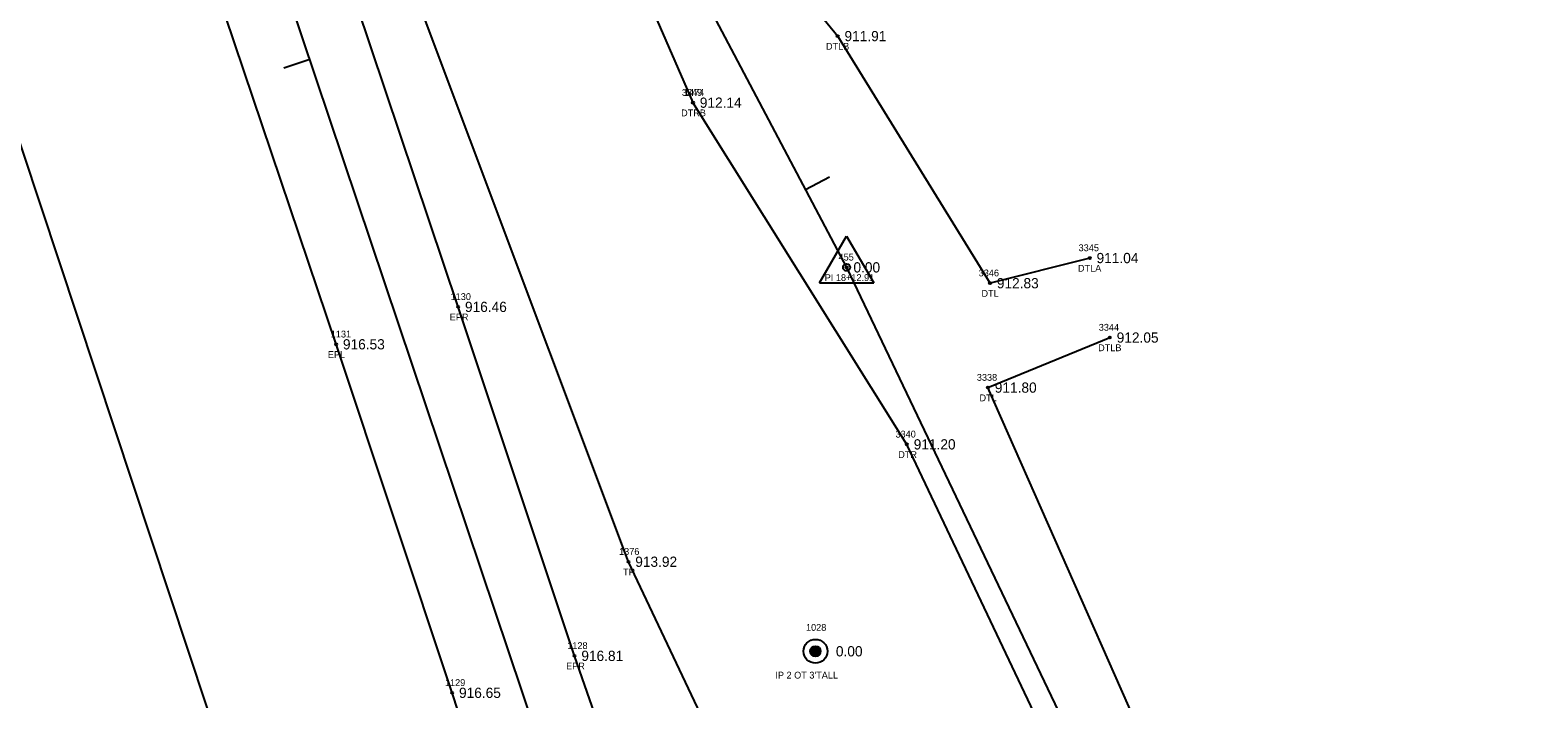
# Model space of a CAD drawing. Extents: x 1528109 to 1531398, y 1157799 to 1162548.
# Drawn here: x 1529538.8 to 1529759.7, y 1160387.6 to 1160485.7 of the extents above; entities that cross this region are included whole.
import ezdxf

# ---------------------------------------------------------------- set-up
doc = ezdxf.new("R2010")
doc.units = 0
for name, color, linetype in [('RD_EX_DV_Prop_txCode', 7, 'Continuous'), ('RD_EX_DV_PropPin', 7, 'Continuous'), ('RD_EX_H2O', 7, 'Continuous'), ('RD_EX_H2O_txCode', 7, 'Continuous'), ('RD_EX_Road', 7, 'Continuous'), ('RD_EX_Road_txCode', 7, 'Continuous'), ('RD_EX_TX_DV_Prop_ELEV', 7, 'Continuous'), ('RD_EX_TX_H2O_ELEV', 7, 'Continuous'), ('RD_EX_TX_Road_ELEV', 7, 'Continuous'), ('RD_EX_TX_VEG_ELEV', 7, 'Continuous'), ('RD_EX_VEG', 7, 'Continuous'), ('RD_EX_VEG_txCode', 7, 'Continuous'), ('RD_HC_Cl', 7, 'Continuous'), ('RD_HC_Data', 7, 'Continuous'), ('RD_HC_Data_Tic', 7, 'Continuous'), ('RD_HC_Survey_ELEV', 7, 'Continuous'), ('RD_HC_txCode', 7, 'Continuous'), ('RD_SMD_Locator', 7, 'Continuous')]:
    doc.layers.add(name, color=color, linetype=linetype)

msp = doc.modelspace()

# ---------------------------------------------------------------- linework, layer by layer
at = {"layer": 'RD_EX_DV_PropPin'}
for p, q in [((1529653.09, 1160394.39), (1529653.09, 1160394.78)), ((1529653.12, 1160394.29), (1529653.12, 1160394.89)), ((1529653.16, 1160394.22), (1529653.16, 1160394.96)), ((1529653.19, 1160394.16), (1529653.19, 1160395.01)), ((1529653.23, 1160394.11), (1529653.23, 1160395.06)), ((1529653.26, 1160394.07), (1529653.26, 1160395.1)), ((1529653.3, 1160394.04), (1529653.3, 1160395.14)), ((1529653.33, 1160394.01), (1529653.33, 1160395.17)), ((1529653.37, 1160393.98), (1529653.37, 1160395.2)), ((1529653.4, 1160393.95), (1529653.4, 1160395.22)), ((1529653.44, 1160393.93), (1529653.44, 1160395.24)), ((1529653.47, 1160393.91), (1529653.47, 1160395.26)), ((1529653.51, 1160393.89), (1529653.51, 1160395.28)), ((1529653.54, 1160393.88), (1529653.54, 1160395.3)), ((1529653.58, 1160393.87), (1529653.58, 1160395.31)), ((1529653.61, 1160393.86), (1529653.61, 1160395.32)), ((1529653.65, 1160393.85), (1529653.65, 1160395.33)), ((1529653.68, 1160393.84), (1529653.68, 1160395.34)), ((1529653.72, 1160393.83), (1529653.72, 1160395.34)), ((1529653.75, 1160393.83), (1529653.75, 1160395.35)), ((1529653.79, 1160393.83), (1529653.79, 1160395.35)), ((1529653.82, 1160393.83), (1529653.82, 1160395.35)), ((1529653.86, 1160393.83), (1529653.86, 1160395.35)), ((1529653.89, 1160393.83), (1529653.89, 1160395.35)), ((1529653.93, 1160393.83), (1529653.93, 1160395.34)), ((1529653.96, 1160393.84), (1529653.96, 1160395.34)), ((1529654, 1160393.85), (1529654, 1160395.33)), ((1529654.03, 1160393.86), (1529654.03, 1160395.32)), ((1529654.07, 1160393.87), (1529654.07, 1160395.31)), ((1529654.1, 1160393.88), (1529654.1, 1160395.3)), ((1529654.14, 1160393.89), (1529654.14, 1160395.28)), ((1529654.17, 1160393.91), (1529654.17, 1160395.26)), ((1529654.21, 1160393.93), (1529654.21, 1160395.24)), ((1529654.24, 1160393.95), (1529654.24, 1160395.22)), ((1529654.28, 1160393.98), (1529654.28, 1160395.2)), ((1529654.31, 1160394.01), (1529654.31, 1160395.17)), ((1529654.35, 1160394.04), (1529654.35, 1160395.14)), ((1529654.38, 1160394.07), (1529654.38, 1160395.1)), ((1529654.42, 1160394.11), (1529654.42, 1160395.06)), ((1529654.45, 1160394.16), (1529654.45, 1160395.01)), ((1529654.49, 1160394.22), (1529654.49, 1160394.96)), ((1529654.52, 1160394.29), (1529654.52, 1160394.89)), ((1529654.56, 1160394.39), (1529654.56, 1160394.78))]:
    msp.add_line(p, q, dxfattribs=at)
for radius in [1.75, 0.761]:
    msp.add_circle((1529653.82, 1160394.59), radius, dxfattribs=at)
at = {"layer": 'RD_EX_H2O'}
for points in [[(1529598.94, 1160572.79), (1529622.38, 1160527.22), (1529657.08, 1160484.79)], [(1529591.59, 1160568.48), (1529614.58, 1160524.05), (1529635.88, 1160475.03)], [(1529694.01, 1160452.25), (1529679.4, 1160448.56), (1529657.08, 1160484.79)], [(1529721.68, 1160311.69), (1529699.45, 1160356.92), (1529667.22, 1160424.93), (1529635.88, 1160475.03)], [(1529726.41, 1160311.29), (1529711.44, 1160359.97), (1529679.1, 1160433.25), (1529696.96, 1160440.59)]]:
    msp.add_lwpolyline(points, dxfattribs=at)
at = {"layer": 'RD_EX_Road'}
for points in [[(1529638.19, 1160337.41), (1529618.52, 1160393.92), (1529601.47, 1160445.09), (1529582.35, 1160502.18), (1529566.78, 1160548.91), (1529548.34, 1160605.67), (1529547.84, 1160613.14)], [(1529619.36, 1160331.12), (1529600.6, 1160388.5), (1529583.59, 1160439.6), (1529564.67, 1160495.86), (1529548.92, 1160543.15), (1529530.19, 1160599.08), (1529525.69, 1160605.63)]]:
    msp.add_lwpolyline(points, dxfattribs=at)
at = {"layer": 'RD_EX_VEG'}
for points in [[(1529712.92, 1160313.49), (1529665.06, 1160326.09), (1529626.42, 1160407.72), (1529580.03, 1160531.48), (1529510.74, 1160760.21), (1529455.97, 1160902.21), (1529420.7, 1161006.64), (1529376.36, 1161143.49), (1529336.53, 1161275.85), (1529306.04, 1161391.66)], [(1529543.38, 1160321.88), (1529583.48, 1160329.53), (1529467.47, 1160679.92), (1529425.09, 1160802.81), (1529349.9, 1161010.59), (1529312.85, 1161137.15)]]:
    msp.add_lwpolyline(points, dxfattribs=at)
at = {"layer": 'RD_HC_Cl'}
for p, q in [((1529913.5, 1159487.74), (1529527.85, 1160635.77)), ((1529598.3, 1160564.55), (1529658.39, 1160450.88)), ((1529658.39, 1160450.88), (1529753.92, 1160250.44))]:
    msp.add_line(p, q, dxfattribs=at)
at = {"layer": 'RD_HC_Data'}
for p, q in [((1529654.42, 1160448.59), (1529658.39, 1160455.47)), ((1529658.39, 1160455.47), (1529662.36, 1160448.59)), ((1529654.42, 1160448.59), (1529662.36, 1160448.59))]:
    msp.add_line(p, q, dxfattribs=at)
msp.add_circle((1529658.39, 1160450.88), 0.529, dxfattribs=at)
at = {"layer": 'RD_HC_Data_Tic'}
for p, q in [((1529579.72, 1160481.35), (1529575.93, 1160480.08)), ((1529652.36, 1160462.29), (1529655.89, 1160464.16))]:
    msp.add_line(p, q, dxfattribs=at)
at = {"layer": 'RD_SMD_Locator'}
for centre in [(1529657.08, 1160484.79), (1529657.08, 1160484.79), (1529635.88, 1160475.03), (1529635.88, 1160475.03), (1529694.01, 1160452.25), (1529658.39, 1160450.88), (1529679.4, 1160448.56), (1529601.47, 1160445.09), (1529696.96, 1160440.59), (1529583.59, 1160439.6), (1529679.1, 1160433.25), (1529667.22, 1160424.93), (1529626.42, 1160407.72), (1529653.82, 1160394.59), (1529618.52, 1160393.92), (1529600.6, 1160388.5)]:
    msp.add_circle(centre, 0.15, dxfattribs=at)

# ---------------------------------------------------------------- texts
at = {"layer": 'RD_EX_DV_Prop_txCode'}
for s, p in [('1028', (1529652.44, 1160397.59)), ("IP 2 OT 3'TALL", (1529647.95, 1160390.59))]:
    msp.add_text(s, height=1, dxfattribs=at).set_placement(p)
at = {"layer": 'RD_EX_H2O_txCode'}
for s, p in [('DTLB', (1529655.36, 1160482.79)), ('DTLB', (1529655.36, 1160482.79)), ('3349', (1529634.25, 1160476.03)), ('1474', (1529634.54, 1160476.03)), ('DTRB', (1529634.14, 1160473.03)), ('DTRB', (1529634.14, 1160473.03)), ('3345', (1529692.38, 1160453.25)), ('3346', (1529677.74, 1160449.56)), ('DTLA', (1529692.28, 1160450.25)), ('DTL', (1529678.15, 1160446.56)), ('3344', (1529695.33, 1160441.59)), ('DTLB', (1529695.24, 1160438.59)), ('3338', (1529677.47, 1160434.25)), ('DTL', (1529677.86, 1160431.25)), ('3340', (1529665.55, 1160425.93)), ('DTR', (1529665.95, 1160422.93))]:
    msp.add_text(s, height=1, dxfattribs=at).set_placement(p)
at = {"layer": 'RD_EX_Road_txCode'}
for s, p in [('1130', (1529600.37, 1160446.09)), ('EPR', (1529600.24, 1160443.09)), ('1131', (1529582.81, 1160440.6)), ('EPL', (1529582.38, 1160437.6)), ('1128', (1529617.46, 1160394.92)), ('EPR', (1529617.29, 1160391.92)), ('1129', (1529599.54, 1160389.5))]:
    msp.add_text(s, height=1, dxfattribs=at).set_placement(p)
at = {"layer": 'RD_EX_TX_DV_Prop_ELEV'}
msp.add_text('0.00', height=1.5, dxfattribs=at).set_placement((1529656.82, 1160393.84))
at = {"layer": 'RD_EX_TX_H2O_ELEV'}
for s, p in [('911.91', (1529658.08, 1160484.04)), ('911.91', (1529658.08, 1160484.04)), ('912.14', (1529636.88, 1160474.28)), ('912.14', (1529636.88, 1160474.28)), ('911.04', (1529695.01, 1160451.5)), ('912.83', (1529680.4, 1160447.81)), ('912.05', (1529697.96, 1160439.84)), ('911.80', (1529680.1, 1160432.5)), ('911.20', (1529668.22, 1160424.18))]:
    msp.add_text(s, height=1.5, dxfattribs=at).set_placement(p)
at = {"layer": 'RD_EX_TX_Road_ELEV'}
for s, p in [('916.46', (1529602.47, 1160444.34)), ('916.53', (1529584.59, 1160438.85)), ('916.81', (1529619.52, 1160393.17)), ('916.65', (1529601.6, 1160387.75))]:
    msp.add_text(s, height=1.5, dxfattribs=at).set_placement(p)
at = {"layer": 'RD_EX_TX_VEG_ELEV'}
msp.add_text('913.92', height=1.5, dxfattribs=at).set_placement((1529627.42, 1160406.97))
at = {"layer": 'RD_EX_VEG_txCode'}
for s, p in [('1376', (1529625.05, 1160408.72)), ('TR', (1529625.63, 1160405.72))]:
    msp.add_text(s, height=1, dxfattribs=at).set_placement(p)
at = {"layer": 'RD_HC_Survey_ELEV'}
msp.add_text('0.00', height=1.5, dxfattribs=at).set_placement((1529659.39, 1160450.13))
at = {"layer": 'RD_HC_txCode'}
for s, p in [('455', (1529657.21, 1160451.88)), ('PI 18+12.91', (1529655.18, 1160448.88))]:
    msp.add_text(s, height=1, dxfattribs=at).set_placement(p)

doc.saveas('drawing.dxf')
